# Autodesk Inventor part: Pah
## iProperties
Company: Autodesk, Inc.
Shininess: 64.0
Length Units: 11269
Angle Units: 11279
Time Units: 11290
Mass Units: 11283
Length Display Precision: 3
Angle Display Precision: 2
Compacted: True
Part Number: Pah
Document SubType Name: Modeling
Created: 2003-11
Designer: Administrator
Manufacturer: Standard
Standards Organization: Custom
Catalog Web Link: www.autodesk.com
Vendor: Autodesk, Inc.
Density: 1 g/cm^3
Density: 0.0
Volumn: 0.0
Area: 0.0
PropertySet Name: Model Information
Control State: 0
Master: False
Checked Out: False
Author: Administrator
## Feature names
1. Extrusion5
2. Extrusion6
3. Extrusion7
4. Hole1
5. Hole2
